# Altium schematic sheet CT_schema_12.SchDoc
size 386 x 278 mm
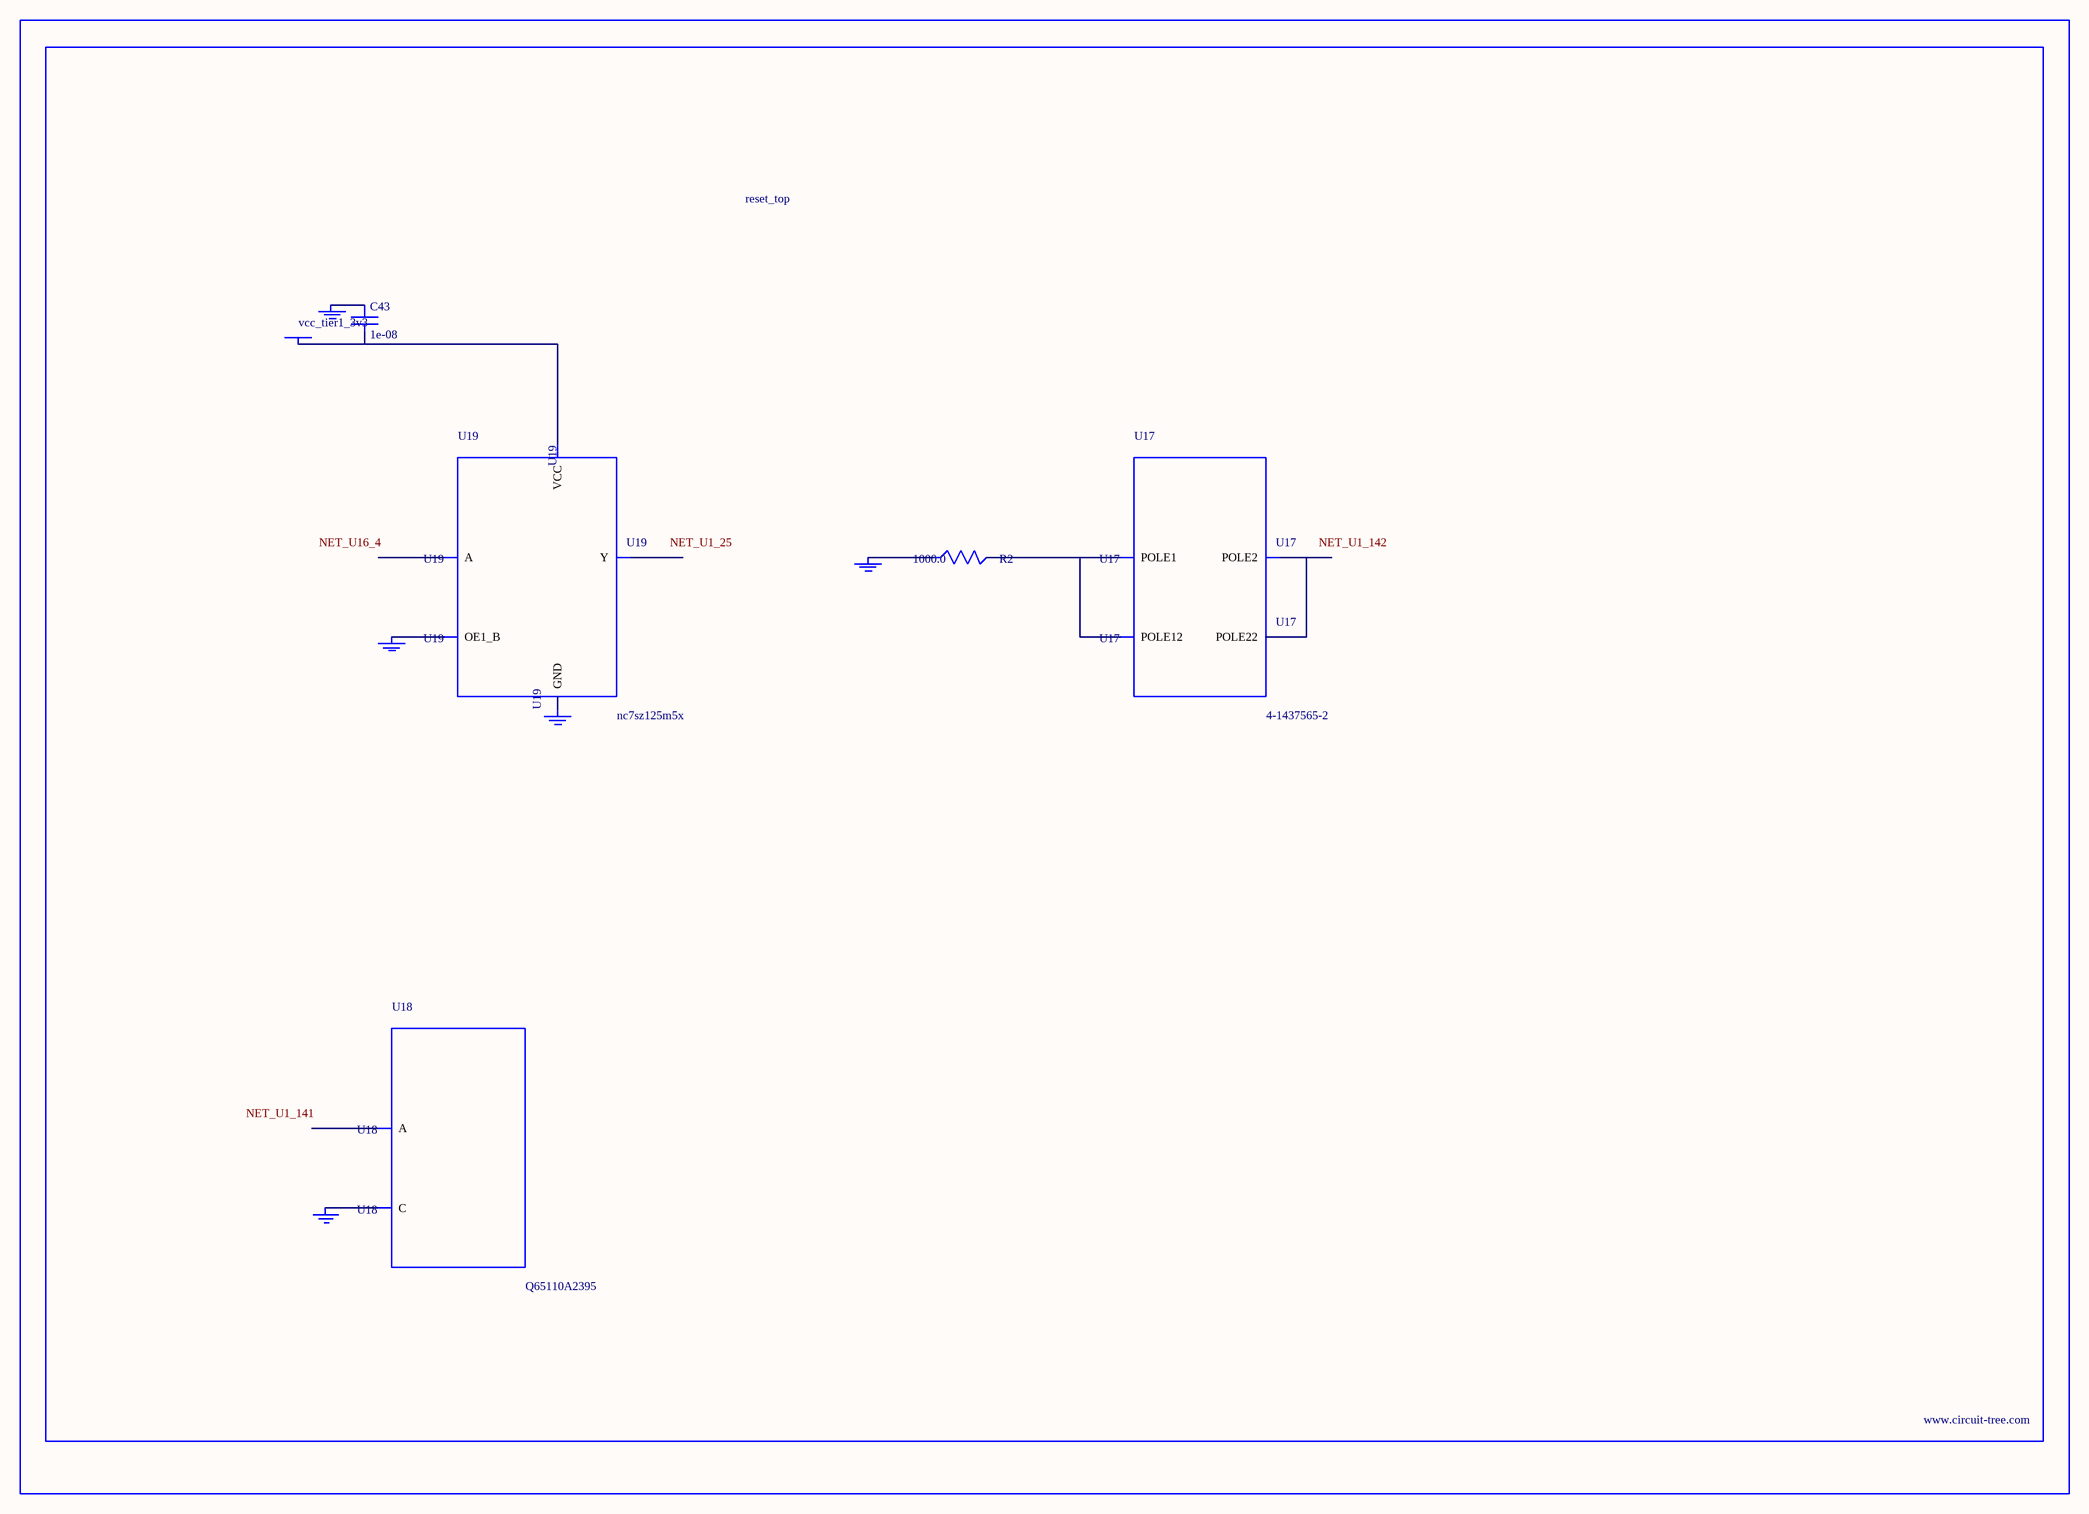
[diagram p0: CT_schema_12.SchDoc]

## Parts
BORDER11  (no value)
C43  1e-08  [C0402]
GND_INSTANCE_11_0  (no value)
GND_INSTANCE_11_1  (no value)
GND_INSTANCE_11_2  (no value)
GND_INSTANCE_11_3  (no value)
GND_INSTANCE_11_4  (no value)
POWER_INSTANCE_11_0  vcc_tier1_3v3
R2  1000.0  [R0603]
U17  4-1437565-2  [SW_4-1437565-2]
U18  Q65110A2395  [LGM67K-G1J2-24-Z]
U19  nc7sz125m5x  [NC7SZ125M5X]

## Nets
NetC43_1: C43.1 GND_INSTANCE_11_2.0(GND)
NetC43_2: C43.2 POWER_INSTANCE_11_0.0(PWR) U19.5(VCC)
NetGND_INSTANCE_11_0_0: GND_INSTANCE_11_0.0(GND) R2.1
NetGND_INSTANCE_11_1_0: GND_INSTANCE_11_1.0(GND) U18.C
NetGND_INSTANCE_11_3_0: GND_INSTANCE_11_3.0(GND) U19.1(OE1_B)
NetGND_INSTANCE_11_4_0: GND_INSTANCE_11_4.0(GND) U19.3(GND)
NetR2_2: R2.2 U17.1(POLE1) U17.2(POLE12)
NetU17_3: U17.3(POLE2) U17.4(POLE22)

Not connected (* = marked no-connect by the designer): U18 A; U19 2(A) 4(Y)

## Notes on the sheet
- Labels drawn without touching a wire or pin: NET_U1_25, NET_U1_141, NET_U1_142, NET_U16_4

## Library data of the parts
BORDER11 = BORDER_PAGE11
C43 = C0402C103K3RAC
GND_INSTANCE_11_0-GND_INSTANCE_11_4 = GND
POWER_INSTANCE_11_0 = PWR
R2 = RC0603JR-071KL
